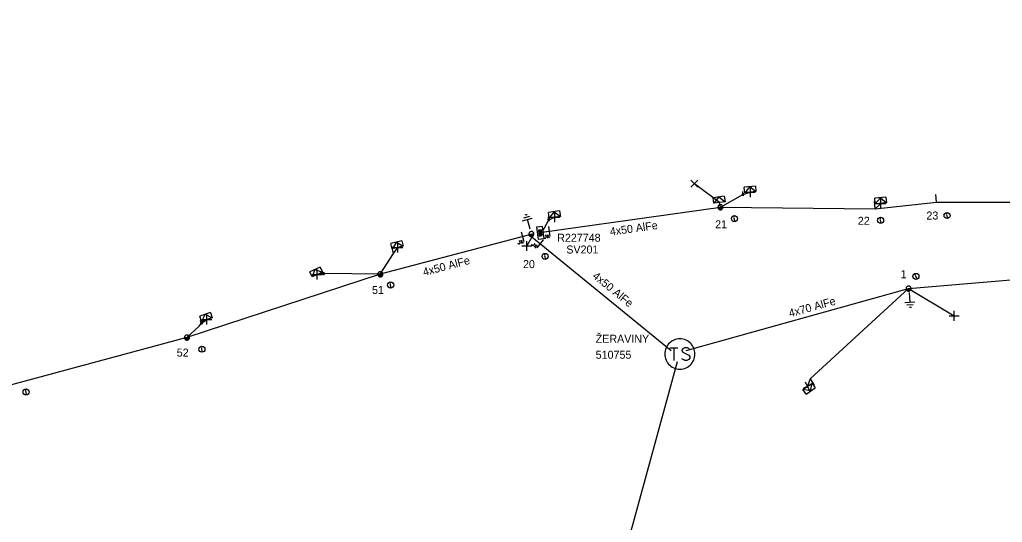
# Model space of a CAD drawing. Extents: x -544780 to -541582, y -1198995 to -1196551.
# Drawn here: x -544561 to -544438.2, y -1198376 to -1198313.1 of the extents above; entities that cross this region are included whole.
import ezdxf

# ---------------------------------------------------------------- set-up
doc = ezdxf.new("R2010")
doc.units = 0
for name, color, linetype in [('Vrstva 1', 7, 'Continuous'), ('Vrstva 10', 7, 'Continuous'), ('Vrstva 13', 7, 'Continuous'), ('Vrstva 14', 7, 'Continuous'), ('Vrstva 15', 7, 'Continuous'), ('Vrstva 18', 7, 'Continuous'), ('Vrstva 2', 7, 'Continuous'), ('Vrstva 25', 7, 'Continuous'), ('Vrstva 26', 7, 'Continuous'), ('Vrstva 27', 7, 'Continuous'), ('Vrstva 28', 7, 'Continuous'), ('Vrstva 29', 7, 'Continuous'), ('Vrstva 30', 7, 'Continuous'), ('Vrstva 31', 7, 'Continuous'), ('Vrstva 34', 7, 'Continuous'), ('Vrstva 36', 7, 'Continuous'), ('Vrstva 54', 7, 'Continuous'), ('Vrstva 59', 7, 'Continuous'), ('Vrstva 6', 7, 'Continuous'), ('Vrstva 8', 7, 'Continuous'), ('Vrstva 9', 7, 'Continuous')]:
    doc.layers.add(name, color=color, linetype=linetype)

# ---------------------------------------------------------------- blocks, each defined once
blk = doc.blocks.new('NN440')
at = {"layer": 'Vrstva 2'}
for points in [[(0.63, 0), (0.63, 0.06), (0.62, 0.13), (0.6, 0.19), (0.58, 0.25), (0.55, 0.31), (0.51, 0.37), (0.47, 0.42), (0.42, 0.46), (0.37, 0.51), (0.32, 0.54), (0.26, 0.57), (0.2, 0.59), (0.13, 0.61), (0.07, 0.62), (0, 0.63), (-0.06, 0.62), (-0.13, 0.61), (-0.19, 0.59), (-0.26, 0.57), (-0.31, 0.54), (-0.37, 0.51), (-0.42, 0.46), (-0.47, 0.42), (-0.51, 0.37), (-0.54, 0.31), (-0.57, 0.25), (-0.6, 0.19), (-0.62, 0.13), (-0.63, 0.06), (-0.63, 0), (-0.63, -0.07), (-0.62, -0.14), (-0.6, -0.2), (-0.57, -0.26), (-0.54, -0.32), (-0.51, -0.37), (-0.47, -0.43), (-0.42, -0.47), (-0.37, -0.51), (-0.31, -0.55), (-0.26, -0.58), (-0.19, -0.6), (-0.13, -0.62), (-0.06, -0.63), (0, -0.63), (0.07, -0.63), (0.13, -0.62), (0.2, -0.6), (0.26, -0.58), (0.32, -0.55), (0.37, -0.51), (0.42, -0.47), (0.47, -0.43), (0.51, -0.37), (0.55, -0.32), (0.58, -0.26), (0.6, -0.2), (0.62, -0.14), (0.63, -0.07), (0.63, 0)], [(-0.63, 0), (0.63, 0)], [(-0.6, -0.18), (0.57, -0.18)], [(-0.51, -0.32), (0.5, -0.32)], [(-0.37, -0.47), (0.35, -0.47)]]:
    blk.add_lwpolyline(points, dxfattribs=at)
blk = doc.blocks.new('NN840')
at = {"layer": 'Vrstva 15'}
for points in [[(0, 0.62), (0, -0.63)], [(-0.75, -0.71), (-0.75, -0.66)], [(-0.73, -0.76), (-0.75, -0.71)], [(-0.66, -0.8), (-0.73, -0.76)], [(-0.63, -0.8), (-0.66, -0.8)], [(-0.56, -0.76), (-0.63, -0.8)], [(-0.54, -0.71), (-0.56, -0.76)], [(-0.54, -0.38), (-0.54, -0.71)], [(-0.33, -0.38), (-0.33, -0.8)], [(-0.33, -0.64), (-0.13, -0.38)], [(-0.26, -0.56), (-0.09, -0.8)]]:
    blk.add_lwpolyline(points, dxfattribs=at)
blk = doc.blocks.new('NN770')
at = {"layer": 'Vrstva 10'}
for p, q in [((0, 0.19), (0, 0.26)), ((0, -0.28), (0, 0.11))]:
    blk.add_line(p, q, dxfattribs=at)
blk.add_circle((0, -0.01), 0.375, dxfattribs=at)
blk = doc.blocks.new('NN800')
at = {"layer": 'Vrstva 1'}
for points in [[(-0.44, 0.44), (0.44, -0.44)], [(-0.44, -0.44), (0.44, 0.44)]]:
    blk.add_lwpolyline(points, dxfattribs=at)
blk = doc.blocks.new('NN620')
at = {"layer": 'Vrstva 8'}
for points in [[(0.75, 0), (-0.75, 0)], [(-0.75, 0), (-0.75, -0.75)], [(0.75, -0.75), (0.75, 0)], [(-0.75, -0.75), (0.75, -0.75)], [(0.37, -0.18), (-0.38, -0.18)], [(-0.38, -0.18), (-0.38, -0.56)], [(-0.38, -0.56), (0.37, -0.56)], [(0.32, -0.23), (-0.33, -0.23)], [(-0.33, -0.23), (-0.33, -0.51)], [(-0.33, -0.51), (0.32, -0.51)], [(0.27, -0.27), (-0.28, -0.27)], [(-0.28, -0.27), (-0.28, -0.46)], [(-0.28, -0.46), (0.27, -0.46)], [(0.23, -0.32), (-0.23, -0.32)], [(-0.23, -0.32), (-0.23, -0.42)], [(-0.23, -0.42), (0.23, -0.42)], [(-0.19, -0.37), (0.19, -0.37)], [(0.23, -0.42), (0.23, -0.32)], [(0.27, -0.46), (0.27, -0.27)], [(0.32, -0.51), (0.32, -0.23)], [(0.37, -0.56), (0.37, -0.18)]]:
    blk.add_lwpolyline(points, dxfattribs=at)
blk = doc.blocks.new('NN630')
at = {"layer": 'Vrstva 9'}
for points in [[(0, -0.7), (-0.7, 0)], [(-0.7, -0.7), (-0.7, 0), (0.7, 0), (0.7, -0.7)], [(-0.7, -0.7), (0.7, -0.7)], [(0, -0.7), (0.7, 0)]]:
    blk.add_lwpolyline(points, dxfattribs=at)
blk = doc.blocks.new('NN810')
at = {"layer": 'Vrstva 14'}
for points in [[(0, -0.64), (0, -1.89)], [(0.63, -1.89), (-0.62, -1.89)], [(0.39, -2.2), (-0.4, -2.2)], [(0, -2.52), (-0.12, -2.52)], [(0.14, -2.52), (0, -2.52)]]:
    blk.add_lwpolyline(points, dxfattribs=at)
blk = doc.blocks.new('NN500')
at = {"layer": 'Vrstva 2'}
for points in [[(0, -0.24), (0.02, -0.23), (0.05, -0.23), (0.07, -0.22), (0.09, -0.22), (0.12, -0.2), (0.14, -0.19), (0.16, -0.18), (0.17, -0.16), (0.19, -0.14), (0.2, -0.12), (0.21, -0.1), (0.22, -0.07), (0.23, -0.05), (0.23, -0.02), (0.23, 0), (0.23, 0.02), (0.23, 0.05), (0.22, 0.07), (0.21, 0.1), (0.2, 0.12), (0.19, 0.14), (0.17, 0.16), (0.16, 0.17), (0.14, 0.19), (0.12, 0.2), (0.09, 0.21), (0.07, 0.22), (0.05, 0.23), (0.02, 0.23), (0, 0.23), (-0.03, 0.23), (-0.05, 0.23), (-0.07, 0.22), (-0.1, 0.21), (-0.12, 0.2), (-0.14, 0.19), (-0.16, 0.17), (-0.18, 0.16), (-0.19, 0.14), (-0.2, 0.12), (-0.22, 0.1), (-0.22, 0.07), (-0.23, 0.05), (-0.23, 0.02), (-0.24, 0), (-0.23, -0.02), (-0.23, -0.05), (-0.22, -0.07), (-0.22, -0.1), (-0.2, -0.12), (-0.19, -0.14), (-0.18, -0.16), (-0.16, -0.18), (-0.14, -0.19), (-0.12, -0.2), (-0.1, -0.22), (-0.07, -0.22), (-0.05, -0.23), (-0.03, -0.23), (0, -0.24)], [(0, -0.24), (0.02, -0.23), (0.05, -0.23), (0.07, -0.22), (0.09, -0.22), (0.12, -0.2), (0.14, -0.19), (0.16, -0.18), (0.17, -0.16), (0.19, -0.14), (0.2, -0.12), (0.21, -0.1), (0.22, -0.07), (0.23, -0.05), (0.23, -0.02), (0.23, 0), (0.23, 0.02), (0.23, 0.05), (0.22, 0.07), (0.21, 0.1), (0.2, 0.12), (0.19, 0.14), (0.17, 0.16), (0.16, 0.17), (0.14, 0.19), (0.12, 0.2), (0.09, 0.21), (0.07, 0.22), (0.05, 0.23), (0.02, 0.23), (0, 0.23), (-0.03, 0.23), (-0.05, 0.23), (-0.07, 0.22), (-0.1, 0.21), (-0.12, 0.2), (-0.14, 0.19), (-0.16, 0.17), (-0.18, 0.16), (-0.19, 0.14), (-0.2, 0.12), (-0.22, 0.1), (-0.22, 0.07), (-0.23, 0.05), (-0.23, 0.02), (-0.24, 0), (-0.23, -0.02), (-0.23, -0.05), (-0.22, -0.07), (-0.22, -0.1), (-0.2, -0.12), (-0.19, -0.14), (-0.18, -0.16), (-0.16, -0.18), (-0.14, -0.19), (-0.12, -0.2), (-0.1, -0.22), (-0.07, -0.22), (-0.05, -0.23), (-0.03, -0.23), (0, -0.24)], [(0, -0.21), (0.02, -0.2), (0.04, -0.2), (0.06, -0.2), (0.08, -0.19), (0.1, -0.18), (0.12, -0.17), (0.14, -0.15), (0.15, -0.14), (0.16, -0.12), (0.18, -0.1), (0.19, -0.08), (0.19, -0.06), (0.2, -0.04), (0.2, -0.02), (0.2, 0), (0.2, 0.02), (0.2, 0.04), (0.19, 0.06), (0.19, 0.08), (0.18, 0.1), (0.16, 0.12), (0.15, 0.14), (0.14, 0.15), (0.12, 0.17), (0.1, 0.18), (0.08, 0.19), (0.06, 0.19), (0.04, 0.2), (0.02, 0.2), (0, 0.2), (-0.02, 0.2), (-0.04, 0.2), (-0.06, 0.19), (-0.08, 0.19), (-0.1, 0.18), (-0.12, 0.17), (-0.14, 0.15), (-0.15, 0.14), (-0.17, 0.12), (-0.18, 0.1), (-0.19, 0.08), (-0.2, 0.06), (-0.2, 0.04), (-0.21, 0.02), (-0.21, 0), (-0.21, -0.02), (-0.2, -0.04), (-0.2, -0.06), (-0.19, -0.08), (-0.18, -0.1), (-0.17, -0.12), (-0.15, -0.14), (-0.14, -0.15), (-0.12, -0.17), (-0.1, -0.18), (-0.08, -0.19), (-0.06, -0.2), (-0.04, -0.2), (-0.02, -0.2), (0, -0.21)], [(0, -0.18), (0.02, -0.18), (0.04, -0.17), (0.05, -0.17), (0.07, -0.16), (0.09, -0.15), (0.1, -0.14), (0.12, -0.13), (0.13, -0.12), (0.14, -0.1), (0.15, -0.09), (0.16, -0.07), (0.17, -0.05), (0.17, -0.04), (0.17, -0.02), (0.17, 0), (0.17, 0.02), (0.17, 0.04), (0.17, 0.05), (0.16, 0.07), (0.15, 0.09), (0.14, 0.1), (0.13, 0.12), (0.12, 0.13), (0.1, 0.14), (0.09, 0.15), (0.07, 0.16), (0.05, 0.17), (0.04, 0.17), (0.02, 0.17), (0, 0.18), (-0.02, 0.17), (-0.04, 0.17), (-0.06, 0.17), (-0.07, 0.16), (-0.09, 0.15), (-0.1, 0.14), (-0.12, 0.13), (-0.13, 0.12), (-0.14, 0.1), (-0.15, 0.09), (-0.16, 0.07), (-0.17, 0.05), (-0.17, 0.04), (-0.18, 0.02), (-0.18, 0), (-0.18, -0.02), (-0.17, -0.04), (-0.17, -0.05), (-0.16, -0.07), (-0.15, -0.09), (-0.14, -0.1), (-0.13, -0.12), (-0.12, -0.13), (-0.1, -0.14), (-0.09, -0.15), (-0.07, -0.16), (-0.06, -0.17), (-0.04, -0.17), (-0.02, -0.18), (0, -0.18)], [(0, -0.15), (0.01, -0.15), (0.03, -0.14), (0.04, -0.14), (0.06, -0.13), (0.07, -0.13), (0.08, -0.12), (0.1, -0.11), (0.11, -0.1), (0.12, -0.09), (0.13, -0.07), (0.13, -0.06), (0.14, -0.05), (0.14, -0.03), (0.14, -0.02), (0.14, 0), (0.14, 0.01), (0.14, 0.03), (0.14, 0.04), (0.13, 0.06), (0.13, 0.07), (0.12, 0.09), (0.11, 0.1), (0.1, 0.11), (0.08, 0.12), (0.07, 0.13), (0.06, 0.13), (0.04, 0.14), (0.03, 0.14), (0.01, 0.14), (0, 0.15), (-0.02, 0.14), (-0.03, 0.14), (-0.05, 0.14), (-0.06, 0.13), (-0.07, 0.13), (-0.09, 0.12), (-0.1, 0.11), (-0.11, 0.1), (-0.12, 0.09), (-0.13, 0.07), (-0.13, 0.06), (-0.14, 0.04), (-0.14, 0.03), (-0.15, 0.01), (-0.15, 0), (-0.15, -0.02), (-0.14, -0.03), (-0.14, -0.05), (-0.13, -0.06), (-0.13, -0.07), (-0.12, -0.09), (-0.11, -0.1), (-0.1, -0.11), (-0.09, -0.12), (-0.07, -0.13), (-0.06, -0.13), (-0.05, -0.14), (-0.03, -0.14), (-0.02, -0.15), (0, -0.15)], [(0, -0.12), (0.01, -0.12), (0.02, -0.11), (0.03, -0.11), (0.05, -0.11), (0.06, -0.1), (0.07, -0.09), (0.08, -0.09), (0.09, -0.08), (0.09, -0.07), (0.1, -0.06), (0.11, -0.05), (0.11, -0.04), (0.11, -0.02), (0.11, -0.01), (0.12, 0), (0.11, 0.01), (0.11, 0.02), (0.11, 0.04), (0.11, 0.05), (0.1, 0.06), (0.09, 0.07), (0.09, 0.08), (0.08, 0.09), (0.07, 0.09), (0.06, 0.1), (0.05, 0.11), (0.03, 0.11), (0.02, 0.11), (0.01, 0.12), (0, 0.12), (-0.01, 0.12), (-0.03, 0.11), (-0.04, 0.11), (-0.05, 0.11), (-0.06, 0.1), (-0.07, 0.09), (-0.08, 0.09), (-0.09, 0.08), (-0.1, 0.07), (-0.1, 0.06), (-0.11, 0.05), (-0.11, 0.04), (-0.12, 0.02), (-0.12, 0.01), (-0.12, 0), (-0.12, -0.01), (-0.12, -0.02), (-0.11, -0.04), (-0.11, -0.05), (-0.1, -0.06), (-0.1, -0.07), (-0.09, -0.08), (-0.08, -0.09), (-0.07, -0.09), (-0.06, -0.1), (-0.05, -0.11), (-0.04, -0.11), (-0.03, -0.11), (-0.01, -0.12), (0, -0.12)], [(0, -0.09), (0.01, -0.09), (0.02, -0.09), (0.03, -0.08), (0.03, -0.08), (0.04, -0.08), (0.05, -0.07), (0.06, -0.07), (0.06, -0.06), (0.07, -0.05), (0.07, -0.04), (0.08, -0.04), (0.08, -0.03), (0.08, -0.02), (0.09, -0.01), (0.09, 0), (0.09, 0.01), (0.08, 0.02), (0.08, 0.03), (0.08, 0.03), (0.07, 0.04), (0.07, 0.05), (0.06, 0.06), (0.06, 0.06), (0.05, 0.07), (0.04, 0.07), (0.03, 0.08), (0.03, 0.08), (0.02, 0.08), (0.01, 0.09), (0, 0.09), (-0.01, 0.09), (-0.02, 0.08), (-0.03, 0.08), (-0.04, 0.08), (-0.04, 0.07), (-0.05, 0.07), (-0.06, 0.06), (-0.07, 0.06), (-0.07, 0.05), (-0.08, 0.04), (-0.08, 0.03), (-0.08, 0.03), (-0.09, 0.02), (-0.09, 0.01), (-0.09, 0), (-0.09, -0.01), (-0.09, -0.02), (-0.08, -0.03), (-0.08, -0.04), (-0.08, -0.04), (-0.07, -0.05), (-0.07, -0.06), (-0.06, -0.07), (-0.05, -0.07), (-0.04, -0.08), (-0.04, -0.08), (-0.03, -0.08), (-0.02, -0.09), (-0.01, -0.09), (0, -0.09)], [(0, -0.06), (0, -0.06), (0.01, -0.06), (0.02, -0.05), (0.02, -0.05), (0.03, -0.05), (0.03, -0.05), (0.04, -0.04), (0.04, -0.04), (0.05, -0.03), (0.05, -0.03), (0.05, -0.02), (0.05, -0.02), (0.05, -0.01), (0.06, -0.01), (0.06, 0), (0.06, 0.01), (0.05, 0.01), (0.05, 0.02), (0.05, 0.02), (0.05, 0.03), (0.05, 0.03), (0.04, 0.04), (0.04, 0.04), (0.03, 0.05), (0.03, 0.05), (0.02, 0.05), (0.02, 0.05), (0.01, 0.06), (0, 0.06), (0, 0.06), (-0.01, 0.06), (-0.01, 0.06), (-0.02, 0.05), (-0.02, 0.05), (-0.03, 0.05), (-0.03, 0.05), (-0.04, 0.04), (-0.04, 0.04), (-0.05, 0.03), (-0.05, 0.03), (-0.05, 0.02), (-0.06, 0.02), (-0.06, 0.01), (-0.06, 0.01), (-0.06, 0), (-0.06, -0.01), (-0.06, -0.01), (-0.06, -0.02), (-0.05, -0.02), (-0.05, -0.03), (-0.05, -0.03), (-0.04, -0.04), (-0.04, -0.04), (-0.03, -0.05), (-0.03, -0.05), (-0.02, -0.05), (-0.02, -0.05), (-0.01, -0.06), (-0.01, -0.06), (0, -0.06)], [(0, -0.03), (0, -0.03), (0, -0.03), (0.01, -0.03), (0.01, -0.03), (0.01, -0.02), (0.02, -0.02), (0.02, -0.02), (0.02, -0.02), (0.02, -0.02), (0.02, -0.01), (0.02, -0.01), (0.03, -0.01), (0.03, -0.01), (0.03, 0), (0.03, 0), (0.03, 0), (0.03, 0.01), (0.03, 0.01), (0.02, 0.01), (0.02, 0.01), (0.02, 0.02), (0.02, 0.02), (0.02, 0.02), (0.02, 0.02), (0.01, 0.02), (0.01, 0.02), (0.01, 0.03), (0, 0.03), (0, 0.03), (0, 0.03), (0, 0.03), (-0.01, 0.03), (-0.01, 0.03), (-0.01, 0.02), (-0.02, 0.02), (-0.02, 0.02), (-0.02, 0.02), (-0.02, 0.02), (-0.02, 0.02), (-0.03, 0.01), (-0.03, 0.01), (-0.03, 0.01), (-0.03, 0.01), (-0.03, 0), (-0.03, 0), (-0.03, 0), (-0.03, -0.01), (-0.03, -0.01), (-0.03, -0.01), (-0.03, -0.01), (-0.02, -0.02), (-0.02, -0.02), (-0.02, -0.02), (-0.02, -0.02), (-0.02, -0.02), (-0.01, -0.03), (-0.01, -0.03), (-0.01, -0.03), (0, -0.03), (0, -0.03)], [(0.23, 0), (0.7, 0)]]:
    blk.add_lwpolyline(points, dxfattribs=at)
blk = doc.blocks.new('NN610')
at = {"layer": 'Vrstva 6'}
for points in [[(1.88, 0), (1.87, 0.2), (1.84, 0.39), (1.79, 0.58), (1.72, 0.77), (1.63, 0.94), (1.52, 1.11), (1.4, 1.26), (1.26, 1.4), (1.1, 1.53), (0.94, 1.63), (0.76, 1.72), (0.58, 1.8), (0.19, 1.88), (0.19, 1.88), (-0.01, 1.89), (-0.21, 1.88), (-0.4, 1.85), (-0.59, 1.8), (-0.78, 1.72), (-0.95, 1.63), (-1.12, 1.53), (-1.27, 1.4), (-1.41, 1.26), (-1.54, 1.11), (-1.64, 0.94), (-1.73, 0.77), (-1.8, 0.58), (-1.86, 0.39), (-1.89, 0.2), (-1.9, 0), (-1.89, -0.2), (-1.86, -0.39), (-1.8, -0.58), (-1.73, -0.77), (-1.64, -0.95), (-1.54, -1.11), (-1.41, -1.27), (-1.27, -1.41), (-1.12, -1.53), (-0.95, -1.64), (-0.78, -1.73), (-0.59, -1.8), (-0.4, -1.85), (-0.21, -1.88), (-0.01, -1.89), (0.19, -1.88), (0.39, -1.85), (0.58, -1.8), (0.76, -1.73), (0.94, -1.64), (1.1, -1.53), (1.26, -1.41), (1.4, -1.27), (1.52, -1.11), (1.63, -0.95), (1.72, -0.77), (1.79, -0.58), (1.84, -0.39), (1.87, -0.2), (1.88, 0)], [(-1.27, 0.78), (-0.26, 0.78)], [(-0.76, 0.78), (-0.76, -0.79)], [(1.19, 0.66), (0.94, 0.78), (0.62, 0.78), (0.37, 0.66), (0.24, 0.47), (0.24, 0.4), (0.37, 0.22), (1.12, -0.16), (1.25, -0.32), (1.25, -0.48), (1.12, -0.67), (0.87, -0.79), (0.62, -0.79), (0.49, -0.73), (0.24, -0.6)]]:
    blk.add_lwpolyline(points, dxfattribs=at)
blk = doc.blocks.new('NN510')
at = {"layer": 'Vrstva 2'}
blk.add_lwpolyline([(0, 0), (0, 0.94)], dxfattribs=at)

msp = doc.modelspace()

# ---------------------------------------------------------------- linework, layer by layer
at = {"layer": 'Vrstva 1'}
for points in [[(-544495.69, -1198339.69), (-544473.41, -1198336.55), (-544454.09, -1198336.76), (-544446.42, -1198335.92), (-544428.57, -1198335.92), (-544412.5, -1198333.1), (-544401.78, -1198331.69), (-544390.61, -1198330.28), (-544368.33, -1198327.41), (-544357.27, -1198325.64), (-544333.1, -1198319.23), (-544322.74, -1198315.67), (-544306.99, -1198313.1)], [(-544477.68, -1198354.46), (-544449.9, -1198346.72), (-544417.97, -1198343.99), (-544389.56, -1198340.94), (-544358.29, -1198337.79), (-544328.73, -1198332.72)], [(-544497.26, -1198339.99), (-544515.91, -1198344.94), (-544540.08, -1198352.85), (-544564.65, -1198359.45), (-544588.16, -1198362.53), (-544608.66, -1198362.97), (-544605.04, -1198395.78), (-544606.03, -1198417.18), (-544617.34, -1198436.38), (-544630.53, -1198460.75)], [(-544479.58, -1198354.49), (-544496.97, -1198340.29)], [(-544478.81, -1198355.9), (-544486.06, -1198382.39)]]:
    msp.add_lwpolyline(points, dxfattribs=at)
at = {"layer": 'Vrstva 54'}
for points in [[(-544473.41, -1198336.55), (-544470.59, -1198334.95), (-544469.67, -1198334.67)], [(-544454.09, -1198336.76), (-544453.36, -1198336.07)], [(-544495.69, -1198339.69), (-544494.86, -1198338.11), (-544494.11, -1198337.81)], [(-544515.91, -1198344.94), (-544514.26, -1198342.33), (-544513.74, -1198341.6)], [(-544515.91, -1198344.94), (-544523, -1198344.86), (-544523.79, -1198344.97)], [(-544449.9, -1198346.72), (-544462.21, -1198358.03), (-544462.53, -1198358.94)], [(-544540.08, -1198352.85), (-544538.56, -1198351.43), (-544538.26, -1198351.04), (-544537.58, -1198350.61)]]:
    msp.add_lwpolyline(points, dxfattribs=at)
at = {"layer": 'Vrstva 59'}
for points in [[(-544473.41, -1198336.55), (-544473.52, -1198335.96), (-544476.66, -1198333.61)], [(-544496.97, -1198340.29), (-544497.6, -1198341.4)], [(-544449.9, -1198346.72), (-544444.2, -1198350.14)]]:
    msp.add_lwpolyline(points, dxfattribs=at)

# ---------------------------------------------------------------- block references
at = {"layer": 'Vrstva 13'}
for name, p, xscale, yscale, rotation in [('NN500', (-544470.59, -1198334.95), 0.5, 0.5, 95.70100004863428), ('NN440', (-544473.41, -1198336.55), 0.4999999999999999, 0.5, 7.360708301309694), ('NN500', (-544494.86, -1198338.11), 0.5000000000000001, 0.5, 97.37200000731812), ('NN440', (-544497.03, -1198339.91), 0.5000000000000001, 0.5, 9.226219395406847), ('NN500', (-544523, -1198344.86), 0.5, 0.5000000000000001, 114.79299999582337), ('NN440', (-544515.91, -1198344.94), 0.5, 0.49999999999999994, 16.877133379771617), ('NN440', (-544449.9, -1198346.72), 0.49999999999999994, 0.5000000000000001, 6.6288194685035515), ('NN500', (-544538.26, -1198351.04), 0.5, 0.5, 108.5699999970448), ('NN440', (-544540.08, -1198352.85), 0.5000000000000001, 0.4999999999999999, 16.708416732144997)]:
    msp.add_blockref(name, p, dxfattribs=dict(at, xscale=xscale, yscale=yscale, rotation=rotation))
for p, rotation in [((-544446.42, -1198335.92), 5.184127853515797), ((-544454.09, -1198336.76), 5.184127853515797), ((-544514.26, -1198342.33), 12.969030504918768), ((-544462.21, -1198358.03), -145.78526113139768)]:
    msp.add_blockref('NN510', p, dxfattribs=dict(at, rotation=rotation))
at = {"layer": 'Vrstva 15'}
for p, rotation in [((-544497.03, -1198339.91), -165.13916107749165), ((-544449.89, -1198346.58), 4.892375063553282)]:
    msp.add_blockref('NN810', p, dxfattribs=dict(at, rotation=rotation))
at = {"layer": 'Vrstva 18'}
for p, rotation in [((-544494.8, -1198339.57), 8.0249750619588), ((-544498.15, -1198340.22), 14.860839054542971), ((-544495.94, -1198341.13), -39.222405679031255)]:
    msp.add_blockref('NN840', p, dxfattribs=dict(at, rotation=rotation))
at = {"layer": 'Vrstva 25', "rotation": -0.03459723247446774}
msp.add_blockref('NN610', (-544478.47, -1198354.91), dxfattribs=at)
at = {"layer": 'Vrstva 28', "rotation": 98.03900005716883}
msp.add_blockref('NN620', (-544496.29, -1198339.81), dxfattribs=at)
at = {"layer": 'Vrstva 31'}
for p, rotation in [((-544469.67, -1198334.67), -174.29869161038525), ((-544473.52, -1198335.96), -171.9750249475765), ((-544453.36, -1198336.07), -174.8158722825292), ((-544494.11, -1198337.81), -172.62752781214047), ((-544513.74, -1198341.6), -167.03096951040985), ((-544523.79, -1198344.97), -155.20713061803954), ((-544537.58, -1198350.61), -161.42981381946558), ((-544462.53, -1198358.94), 34.21473883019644)]:
    msp.add_blockref('NN630', p, dxfattribs=dict(at, rotation=rotation))
at = {"layer": 'Vrstva 34'}
msp.add_blockref('NN800', (-544476.66, -1198333.61), dxfattribs=at)
for p, rotation in [((-544469.67, -1198334.67), 45), ((-544453.36, -1198336.07), 45), ((-544494.11, -1198337.81), 45), ((-544513.74, -1198341.6), 45), ((-544497.6, -1198341.4), 45), ((-544523.79, -1198344.97), 44.99999995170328), ((-544537.58, -1198350.61), 45), ((-544444.2, -1198350.14), 44.99999995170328), ((-544462.53, -1198358.94), -109.16739979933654)]:
    msp.add_blockref('NN800', p, dxfattribs=dict(at, rotation=rotation))
at = {"layer": 'Vrstva 36'}
for p, rotation in [((-544471.66, -1198337.97), 8.038661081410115), ((-544453.39, -1198338.18), 8.038661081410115), ((-544445.09, -1198337.58), 8.03866109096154), ((-544495.32, -1198342.69), 8.038661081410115), ((-544448.98, -1198345.19), 23.31311383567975), ((-544514.62, -1198346.28), 8.038660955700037), ((-544538.2, -1198354.3), 8.038661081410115), ((-544560.18, -1198359.64), 8.038660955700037)]:
    msp.add_blockref('NN770', p, dxfattribs=dict(at, rotation=rotation))

# ---------------------------------------------------------------- texts
at = {"layer": 'Vrstva 14'}
for s, p in [('22', (-544456.24, -1198338.75)), ('23', (-544447.67, -1198338.09)), ('21', (-544474.07, -1198339.19)), ('20', (-544498.08, -1198344.17)), ('1', (-544450.9, -1198345.43)), ('51', (-544516.95, -1198347.4)), ('52', (-544541.35, -1198355.23))]:
    msp.add_text(s, height=1, dxfattribs=at).set_placement(p)
at = {"layer": 'Vrstva 2'}
for s, rotation, p in [('4x50 AlFe', 8.025, (-544487.16, -1198340.11)), ('4x50 AlFe', 14.861, (-544510.45, -1198345.17)), ('4x50 AlFe', 320.778, (-544489.49, -1198345.31)), ('4x70 AlFe', 15.571, (-544464.72, -1198350.32))]:
    msp.add_text(s, height=1, rotation=rotation, dxfattribs=at).set_placement(p)
at = {"layer": 'Vrstva 26'}
msp.add_text('510755', height=1, dxfattribs=at).set_placement((-544489, -1198355.5))
at = {"layer": 'Vrstva 27'}
msp.add_text('ŽERAVINY', height=1, dxfattribs=at).set_placement((-544489, -1198353.5))
at = {"layer": 'Vrstva 29'}
msp.add_text('R227748', height=1, dxfattribs=at).set_placement((-544493.81, -1198340.87))
at = {"layer": 'Vrstva 30'}
msp.add_text('SV201', height=1, dxfattribs=at).set_placement((-544492.67, -1198342.34))

doc.saveas('drawing.dxf')
